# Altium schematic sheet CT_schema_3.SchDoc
size 293 x 134 mm
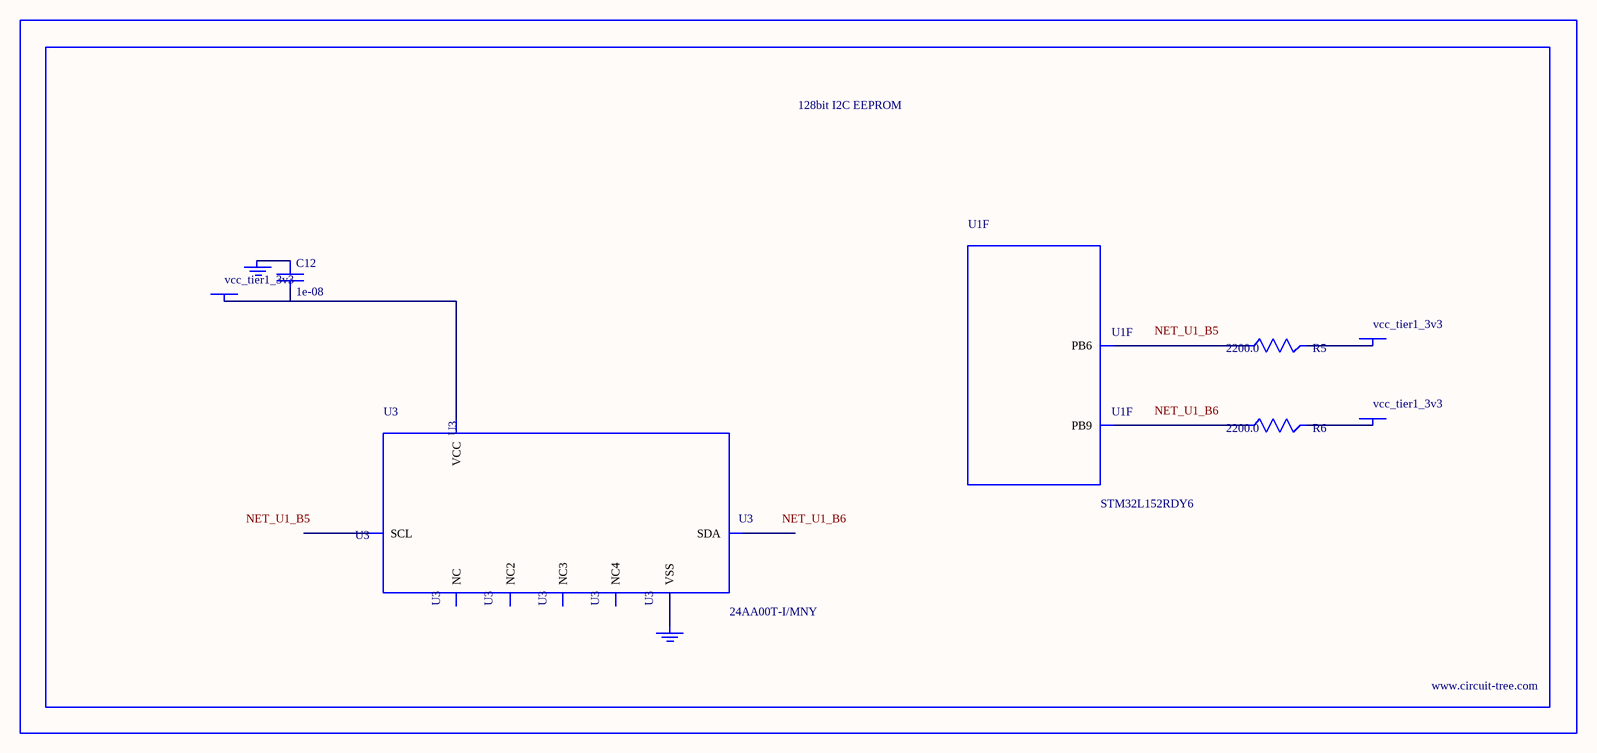
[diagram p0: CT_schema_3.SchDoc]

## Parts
BORDER2  (no value)
C12  1e-08  [C0402]
GND_INSTANCE_2_0  (no value)
GND_INSTANCE_2_1  (no value)
POWER_INSTANCE_2_0  vcc_tier1_3v3
POWER_INSTANCE_2_1  vcc_tier1_3v3
POWER_INSTANCE_2_2  vcc_tier1_3v3
R5  2200.0  [R0603]
R6  2200.0  [R0603]
U1  STM32L152RDY6  [WLCSP64]  (part F of 7)
U3  24AA00T-I/MNY  [TDFN-8/6MM]

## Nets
NetC12_1: C12.1 GND_INSTANCE_2_0.0(GND)
NetC12_2: C12.2 POWER_INSTANCE_2_0.0(PWR) U3.8(VCC)
NetGND_INSTANCE_2_1_0: GND_INSTANCE_2_1.0(GND) U3.4(VSS)
NetPOWER_INSTANCE_2_1_0: POWER_INSTANCE_2_1.0(PWR) R5.2
NetPOWER_INSTANCE_2_2_0: POWER_INSTANCE_2_2.0(PWR) R6.2
NetR5_1: R5.1 U1.B5(PB6)
NetR6_1: R6.1 U1.B6(PB9)

Not connected (* = marked no-connect by the designer): U3 1(NC) 2(NC2) 3(NC3) 5(SDA) 6(SCL) 7(NC4)

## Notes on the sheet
- Labels drawn without touching a wire or pin: NET_U1_B5, NET_U1_B6

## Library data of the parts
BORDER2 = BORDER_PAGE2
C12 = C0402C103K3RAC
GND_INSTANCE_2_0 GND_INSTANCE_2_1 = GND
POWER_INSTANCE_2_0-POWER_INSTANCE_2_2 = PWR
R5 R6 = RC0603JR-072K2L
